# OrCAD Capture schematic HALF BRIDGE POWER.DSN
size A; rev: A
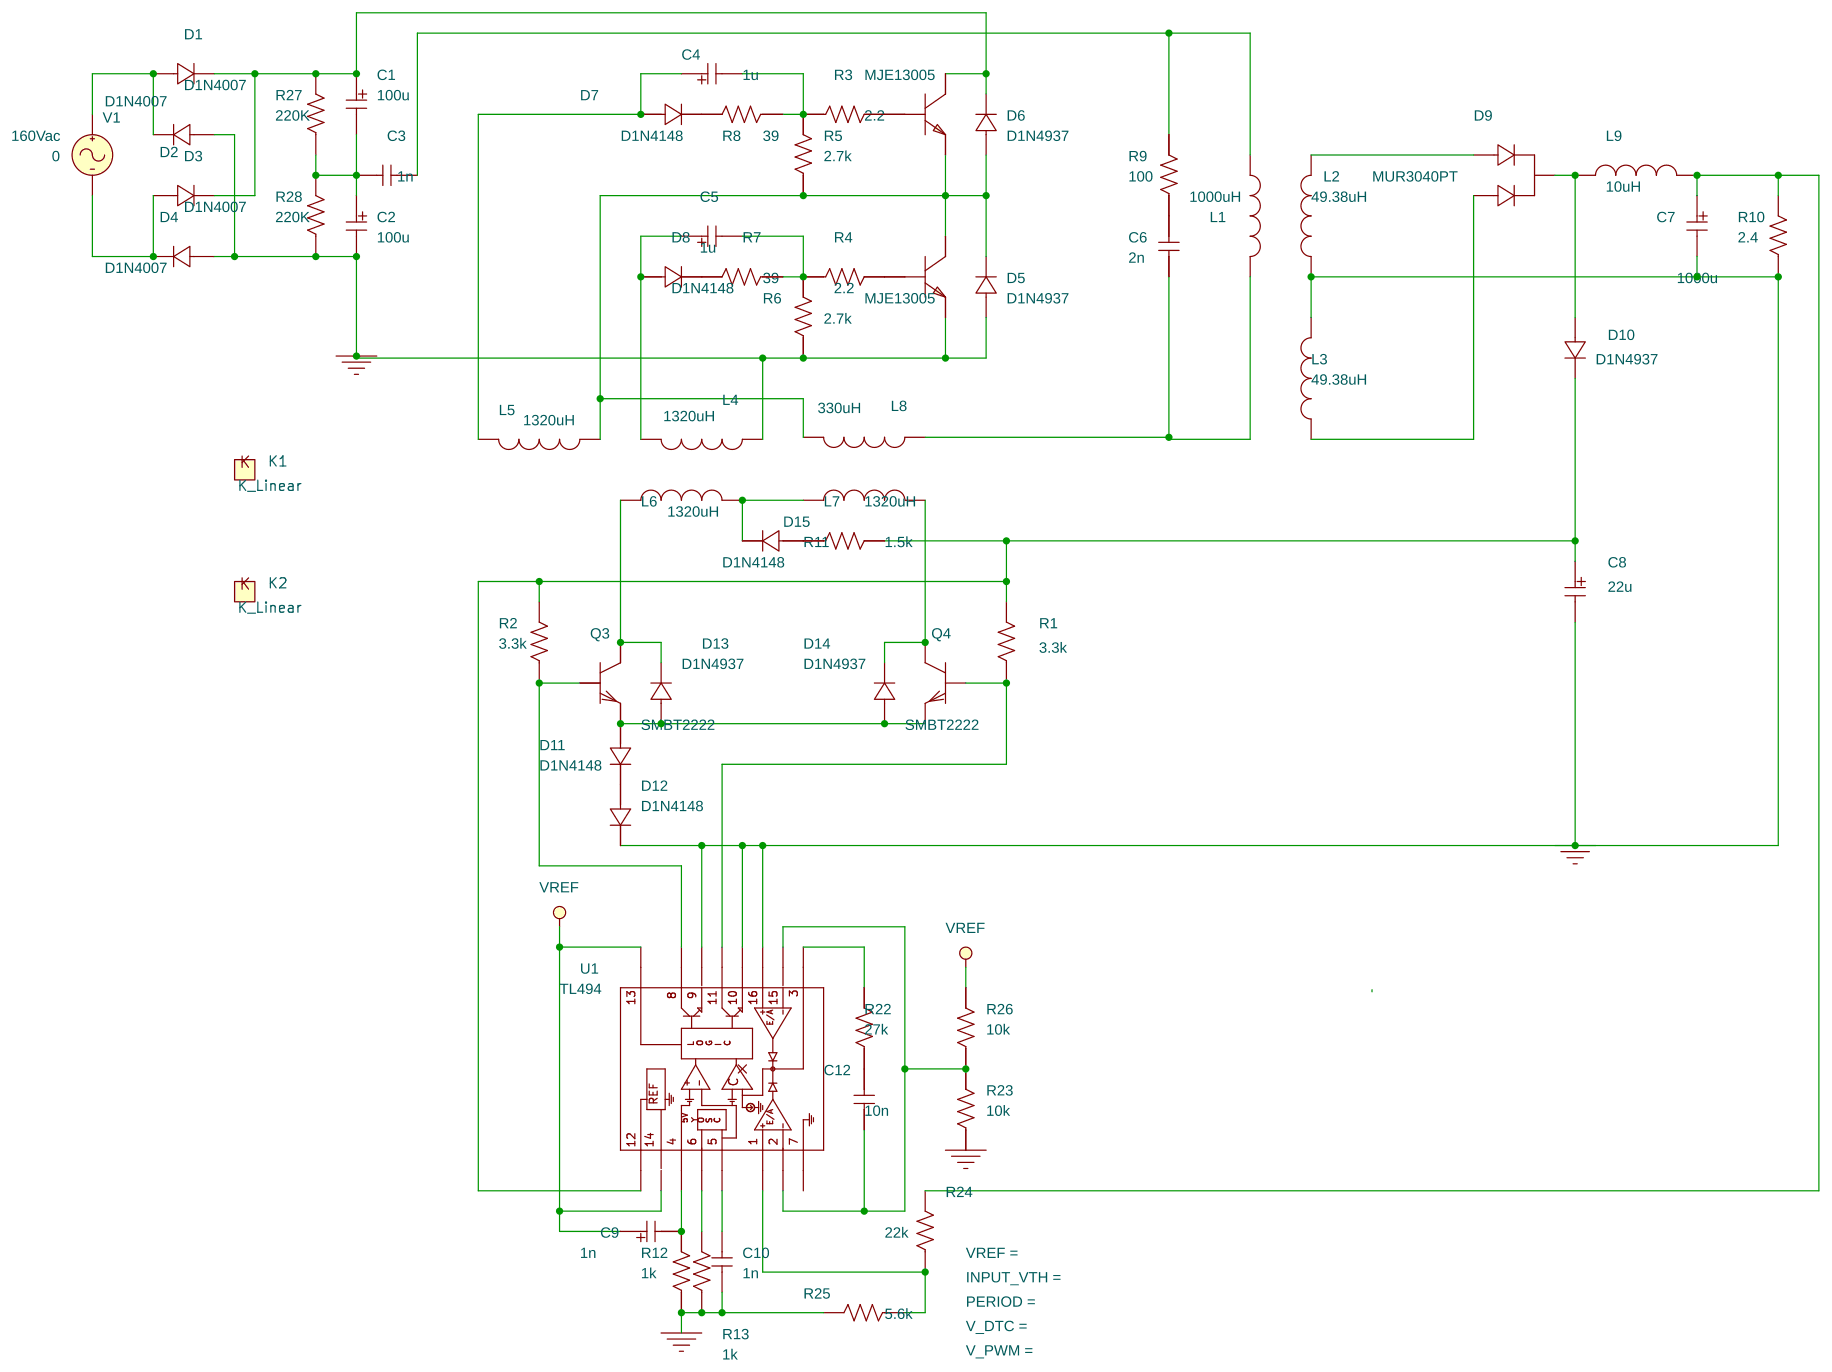
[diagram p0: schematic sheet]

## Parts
C1  100u  [CPAX/.575x.150/.031]
C2  100u  [CPAX/.575x.150/.031]
C3  1n  [RAD/CK05]
C4  1u  [CPAX/.575x.150/.031]
C5  1u  [CPAX/.575x.150/.031]
C6  2n  [RAD/CK05]
C7  1000u  [CPAX/.575x.150/.031]
C8  22u  [CPAX/.575x.150/.031]
C9  1n  [CPAX/.575x.150/.031]
C10  1n  [RAD/CK05]
C12  10n  [RAD/CK05]
D1  D1N4007  [DO-41]
D2  D1N4007  [DO-41]
D3  D1N4007  [DO-41]
D4  D1N4007  [DO-41]
D5  D1N4937  [DO-41]
D6  D1N4937  [DO-41]
D7  D1N4148  [DO-35]
D8  D1N4148  [DO-35]
D9  MUR3040PT  [TO218AC]
D10  D1N4937  [DO-41]
D11  D1N4148  [DO-35]
D12  D1N4148  [DO-35]
D13  D1N4937  [DO-41]
D14  D1N4937  [DO-41]
D15  D1N4148  [DO-35]
K1  K_Linear
K2  K_Linear
L1  1000uH  [DISC/.350x.175/LS.200x.100/.034]
L2  49.38uH  [DISC/.350x.175/LS.200x.100/.034]
L3  49.38uH  [DISC/.350x.175/LS.200x.100/.034]
L4  1320uH  [DISC/.350x.175/LS.200x.100/.034]
L5  1320uH  [DISC/.350x.175/LS.200x.100/.034]
L6  1320uH  [DISC/.350x.175/LS.200x.100/.034]
L7  1320uH  [DISC/.350x.175/LS.200x.100/.034]
L8  330uH  [DISC/.350x.175/LS.200x.100/.034]
L9  10uH  [DISC/.350x.175/LS.200x.100/.034]
Q1  MJE13005
Q2  MJE13005
Q3  SMBT2222  [SOT23]
Q4  SMBT2222  [SOT23]
R1  3.3k  [AX/RC05]
R2  3.3k  [AX/RC05]
R3  2.2  [AX/RC05]
R4  2.2  [AX/RC05]
R5  2.7k  [AX/RC05]
R6  2.7k  [AX/RC05]
R7  39  [AX/RC05]
R8  39  [AX/RC05]
R9  100  [AX/RC05]
R10  2.4  [AX/RC05]
R11  1.5k  [AX/RC05]
R12  1k  [AX/RC05]
R13  1k  [AX/RC05]
R22  27k  [AX/RC05]
R23  10k  [AX/RC05]
R24  22k  [AX/RC05]
R25  5.6k  [AX/RC05]
R26  10k  [AX/RC05]
R27  220K  [AX/RC05]
R28  220K  [AX/RC05]
U1  TL494
V1  VAC

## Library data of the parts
C1 C2 C4 C5 C7-C9 = C_elect
C3 C6 C10 C12 = C
D1-D4 = D1N4007
D5 D6 D10 D13 D14 = D1N4937
D7 D8 D11 D12 D15 = D1N4148
D9 = MUR3040PT
K1 = K_Linear: L1: L1; L2: L2; L3: L3
K2 = K_Linear: L1: L4; L2: L5; L3: L6; L4: L7; L5: L8
L1-L9 = L
Q1 Q2 = MJE13005_TO
Q3 Q4 = SMBT2222
R1-R13 R22-R28 = R
U1 = TL494
V1 = VAC: ACMAG: 160Vac; DC: 0

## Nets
GND: U1.7(GND)
0: C2.N(-) C7.N(-) C8.N(-) C10.1 D2.1 D4.1 D5.1 D12.2 L2.1 L3.2 L4.2 Q1.1(e) R6.1 R10.1 R12.1 R13.1 R23.1 R25.2 R28.1 U1.9(ENA) U1.10(ENB) U1.16(PIN2)
Vref: C9.P(+) R22.2 U1.13(OC) U1.14(VREF)
N80995: C8.P(+) D10.2 R1.2 R2.2 R11.2 U1.12(PVIN)
N81003: D3.1 D4.2 V1.2(-)
N81111: C7.P(+) L9.2 R10.2 R24.2
N81119: D1.1 D2.2 V1.1(+)
N81123: C12.1 R22.1 R23.2 U1.2(NIN1) U1.15(NIN2)
N81371: C1.P(+) D1.2 D3.2 D6.2 Q2.3(c) R27.2
N81403: C1.N(-) C2.P(+) C3.1 R27.1 R28.2
N81423: R13.2 U1.6(RT)
N81455: C10.2 U1.5(CT)
N81523: D5.2 D6.1 L5.2 L8.1 Q1.3(c) Q2.1(e) R5.1
N81691: C5.N(-) R4.1 R6.2 R7.1
N81695: C4.N(-) R3.1 R5.2 R8.1
N81711: D9.2(3) D10.1 L9.1
N81883: R24.1 R25.1 U1.1(PIN1)
N81919: C5.P(+) D8.1 L4.1
N81943: C4.P(+) D7.1 L5.1
N82015: C3.2 L1.1 R9.2
N82067: C6.1 L1.2 L8.2
N82075: D13.2 L6.2 Q3.3(c)
N82115: D14.2 L7.1 Q4.3(c)
N82127: D11.1 D13.1 D14.1 Q3.2(e) Q4.2(e)
N82191: R26.2 U1.3(COMP)
N82259: Q3.1(b) R2.1 U1.8(CNA)
N82275: Q4.1(b) R1.1 U1.11(CNB)
N82487: C9.N(-) R12.2 U1.4(DTC)
N82499: D15.2 L6.1 L7.2
N82897: D9.1 L2.2
N82901: D9.3(2) L3.1
N145168: C12.2 R26.1
N145169: Q2.2(b) R3.2
N145170: C6.2 R9.1
N145172: D11.2 D12.1
N145173: D7.2 R8.2
N145174: D15.1 R11.1
N145175: D8.2 R7.2
N145176: Q1.2(b) R4.2
